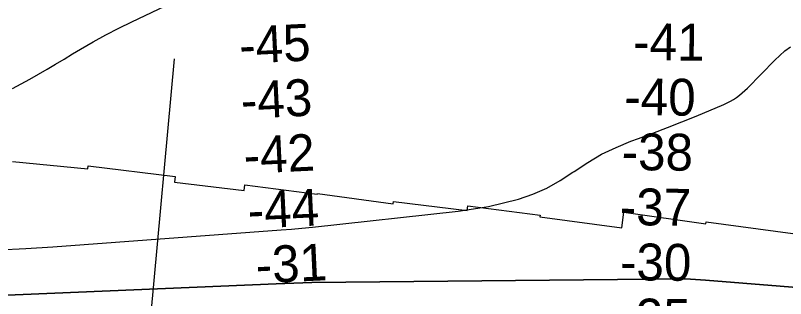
# Model space of a CAD drawing. Extents: x 3329332 to 3367211, y 631066 to 656469.
# Drawn here: x 3334750 to 3336147, y 646028 to 646543 of the extents above; entities that cross this region are included whole.
import ezdxf

# ---------------------------------------------------------------- set-up
doc = ezdxf.new("R2010")
doc.units = 0
for name, color, linetype in [('V-RIVR-RANG', 7, 'Continuous'), ('V-RRAP-RVMT', 7, 'Continuous'), ('V-TOPO-DPTH', 7, 'Continuous'), ('V-TOPO-MAJR', 7, 'Continuous'), ('V-TOPO-MINR', 7, 'Continuous')]:
    doc.layers.add(name, color=color, linetype=linetype)

msp = doc.modelspace()

# ---------------------------------------------------------------- linework, layer by layer
at = {"layer": 'V-RIVR-RANG'}
msp.add_line((3334926.9, 645248.6), (3335038.5, 646463.5), dxfattribs=at)
at = {"layer": 'V-RRAP-RVMT'}
for p, q in [((3334744.1, 646277.2), (3334880.8, 646264.1)), ((3334880.8, 646264.1), (3334881.4, 646269)), ((3334881.4, 646269), (3335039.7, 646250.1)), ((3335039.7, 646250.1), (3335038.4, 646239.7)), ((3335038.4, 646239.7), (3335164.9, 646224.7)), ((3335164.9, 646224.7), (3335166.2, 646234.6)), ((3335166.2, 646234.6), (3335297.4, 646218)), ((3335297.4, 646218), (3335297.6, 646219.3)), ((3335297.6, 646219.3), (3335435.4, 646200.5)), ((3335435.4, 646200.5), (3335435.9, 646204.6)), ((3335435.9, 646204.6), (3335569.7, 646187.9)), ((3335569.7, 646187.9), (3335570.9, 646196.8)), ((3335570.9, 646196.8), (3335702.2, 646179.9)), ((3335702.2, 646179.9), (3335701.7, 646176.6)), ((3335701.7, 646176.6), (3335850.2, 646156.8)), ((3335850.2, 646156.8), (3335854, 646184.9)), ((3335854, 646184.9), (3336002.9, 646164.2)), ((3336002.9, 646164.2), (3336003.3, 646167.5)), ((3336003.3, 646167.5), (3336160.7, 646146.1))]:
    msp.add_line(p, q, dxfattribs=at)
at = {"layer": 'V-TOPO-DPTH'}
for points in [[(3334719, 646116.9), (3334768.4, 646119.4), (3334817.8, 646122.4), (3335231.8, 646152.8), (3335250.8, 646154.4), (3335269.7, 646156.2), (3335288.6, 646158.2), (3335553.3, 646187.2), (3335580.9, 646190.9), (3335608.4, 646195.7), (3335635.6, 646201.8), (3335662.6, 646208.9), (3335688.8, 646218.1), (3335714.1, 646229), (3335738.2, 646242.4), (3335761.5, 646257.5), (3335763.9, 646259.2), (3335788.3, 646275.5), (3335813.4, 646290.2), (3335839.8, 646302.8), (3335866.8, 646314), (3335880.4, 646318.9), (3335906.7, 646328.7), (3335932.9, 646338.8), (3335959, 646349.1), (3335984.9, 646359.8), (3336035.4, 646380.9), (3336041.4, 646383.6), (3336047.2, 646386.6), (3336052.8, 646390), (3336058.2, 646393.6), (3336063.5, 646397.5), (3336068.5, 646401.6), (3336073.4, 646406), (3336078.1, 646410.5), (3336128.1, 646461.2), (3336137.1, 646469.8), (3336146.3, 646477.9), (3336156.1, 646485.6)], [(3334719, 646116.9), (3334768.4, 646119.4), (3334817.8, 646122.4), (3335231.8, 646152.8), (3335250.8, 646154.4), (3335269.7, 646156.2), (3335288.6, 646158.2), (3335553.3, 646187.2), (3335580.9, 646190.9), (3335608.4, 646195.7), (3335635.6, 646201.8), (3335662.6, 646208.9), (3335688.8, 646218.1), (3335714.1, 646229), (3335738.2, 646242.4), (3335761.5, 646257.5), (3335763.9, 646259.2), (3335788.3, 646275.5), (3335813.4, 646290.2), (3335839.8, 646302.8), (3335866.8, 646314), (3335880.4, 646318.9), (3335906.7, 646328.7), (3335932.9, 646338.8), (3335959, 646349.1), (3335984.9, 646359.8), (3336035.4, 646380.9), (3336041.4, 646383.6), (3336047.2, 646386.6), (3336052.8, 646390), (3336058.2, 646393.6), (3336063.5, 646397.5), (3336068.5, 646401.6), (3336073.4, 646406), (3336078.1, 646410.5), (3336128.1, 646461.2), (3336137.1, 646469.8), (3336146.3, 646477.9), (3336156.1, 646485.6)], [(3333442.5, 645992.3), (3333442.4, 646068.3), (3333474, 646069.6), (3333981.4, 646088.3), (3333988.4, 646088.5), (3333995.5, 646088.8), (3334002.5, 646089), (3334572, 646029.4), (3334574.6, 646029), (3334576.7, 646028.9), (3334577, 646028.9), (3334577.4, 646028.9), (3334586.2, 646028.7), (3334591, 646028.7), (3334595.7, 646028.7), (3334600.5, 646028.8), (3334605.2, 646028.9), (3335223.1, 646055.1), (3335255.2, 646056.3), (3335287.4, 646057.3), (3335965.9, 646064), (3336002.3, 646061.4), (3336341.1, 646034.1)], [(3336341.1, 646034.1), (3336002.3, 646061.4), (3335965.9, 646064), (3335287.4, 646057.3), (3335255.2, 646056.3), (3335223.1, 646055.1), (3334605.2, 646028.9), (3334600.5, 646028.8), (3334595.7, 646028.7), (3334591, 646028.7), (3334586.2, 646028.7), (3334577.4, 646028.9), (3334577, 646028.9), (3334576.7, 646028.9), (3334574.6, 646029), (3334572, 646029.4), (3334002.5, 646089), (3333995.5, 646088.8), (3333988.4, 646088.5), (3333981.4, 646088.3), (3333474, 646069.6), (3333442.4, 646068.3)]]:
    msp.add_lwpolyline(points, dxfattribs=at)
at = {"layer": 'V-TOPO-MAJR'}
msp.add_lwpolyline([(3334744.3, 646409.9), (3334760.3, 646418), (3334776.1, 646426.6), (3334791.7, 646435.5), (3334807.1, 646444.7), (3334822.6, 646453.9), (3334838, 646463.2), (3334853.4, 646472.5), (3334867.9, 646481.2), (3334890.7, 646494.6), (3334913.7, 646507.4), (3334937.2, 646519.5), (3334960.9, 646531.1), (3335033.8, 646565.2)], dxfattribs=at)
at = {"layer": 'V-TOPO-MINR'}
for points in [[(3334719, 646116.9), (3334768.4, 646119.4), (3334817.8, 646122.4), (3335231.8, 646152.8), (3335250.8, 646154.4), (3335269.7, 646156.2), (3335288.6, 646158.2), (3335553.3, 646187.2), (3335580.9, 646190.9), (3335608.4, 646195.7), (3335635.6, 646201.8), (3335662.6, 646208.9), (3335688.8, 646218.1), (3335714.1, 646229), (3335738.2, 646242.4), (3335761.5, 646257.5), (3335763.9, 646259.2), (3335788.3, 646275.5), (3335813.4, 646290.2), (3335839.8, 646302.8), (3335866.8, 646314), (3335880.4, 646318.9), (3335906.7, 646328.7), (3335932.9, 646338.8), (3335959, 646349.1), (3335984.9, 646359.8), (3336035.4, 646380.9), (3336041.4, 646383.6), (3336047.2, 646386.6), (3336052.8, 646390), (3336058.2, 646393.6), (3336063.5, 646397.5), (3336068.5, 646401.6), (3336073.4, 646406), (3336078.1, 646410.5), (3336128.1, 646461.2), (3336137.1, 646469.8), (3336146.3, 646477.9), (3336156.1, 646485.6)], [(3333442.4, 646068.3), (3333474, 646069.6), (3333981.4, 646088.3), (3333988.4, 646088.5), (3333995.5, 646088.8), (3334002.5, 646089), (3334572, 646029.4), (3334574.6, 646029), (3334576.7, 646028.9), (3334577, 646028.9), (3334577.4, 646028.9), (3334586.2, 646028.7), (3334591, 646028.7), (3334595.7, 646028.7), (3334600.5, 646028.8), (3334605.2, 646028.9), (3335223.1, 646055.1), (3335255.2, 646056.3), (3335287.4, 646057.3), (3335965.9, 646064), (3336002.3, 646061.4), (3336341.1, 646034.1)]]:
    msp.add_lwpolyline(points, dxfattribs=at)

# ---------------------------------------------------------------- texts
at = {"layer": 'V-RIVR-RANG'}
for s, rotation, p in [('-45', 2.7362, (3335157.2, 646454.5)), ('-41', 359.3641, (3335870.5, 646461.5)), ('-43', 2.7362, (3335160.2, 646354.5)), ('-40', 359.3641, (3335854.4, 646361.6)), ('-42', 2.7362, (3335165.2, 646254.7)), ('-38', 359.3641, (3335849.6, 646261.7)), ('-44', 2.7362, (3335172.7, 646154.9)), ('-37', 359.3641, (3335846.2, 646161.7)), ('-31', 2.7362, (3335187.2, 646055.5)), ('-30', 359.3641, (3335846.6, 646061.7)), ('-25', 359.3641, (3335845, 645961.7))]:
    msp.add_text(s, height=67, rotation=rotation, dxfattribs=at).set_placement(p)

doc.saveas('drawing.dxf')
